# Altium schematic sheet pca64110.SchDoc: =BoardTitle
size A4; Organization: Nordic Semiconductor; SheetNumber: 1; SheetTotal: 1; CompanyName: Nordic Semiconductor; DocumentSize: A4
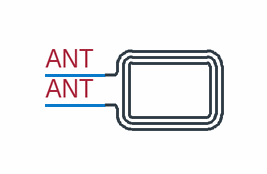
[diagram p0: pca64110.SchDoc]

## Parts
A1  NFC_ANT_Listener-6  [NFC_ANT_Listener-6]  (value not drawn)  (no BOM)

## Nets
ANT: A1.1 A1.2

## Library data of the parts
A1 = NFC_ANT_Listener-6: NFC Antenna Listener-6; Manufacturer: N.A.; Pad Count: 2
